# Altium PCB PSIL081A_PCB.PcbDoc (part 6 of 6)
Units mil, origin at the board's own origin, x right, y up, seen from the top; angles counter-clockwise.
Board outline 14000 x 8000 mil, 10 copper layers (Top Layer, Signal Layer 1, Signal Layer 2, Signal Layer 3, Signal Layer 4, Signal Layer 5, Signal Layer 6, Signal Layer 7, Signal Layer 8, Bottom Layer), stack 60.9 mil thick; 433 components, 510 nets, 1716 pads, 590 vias.
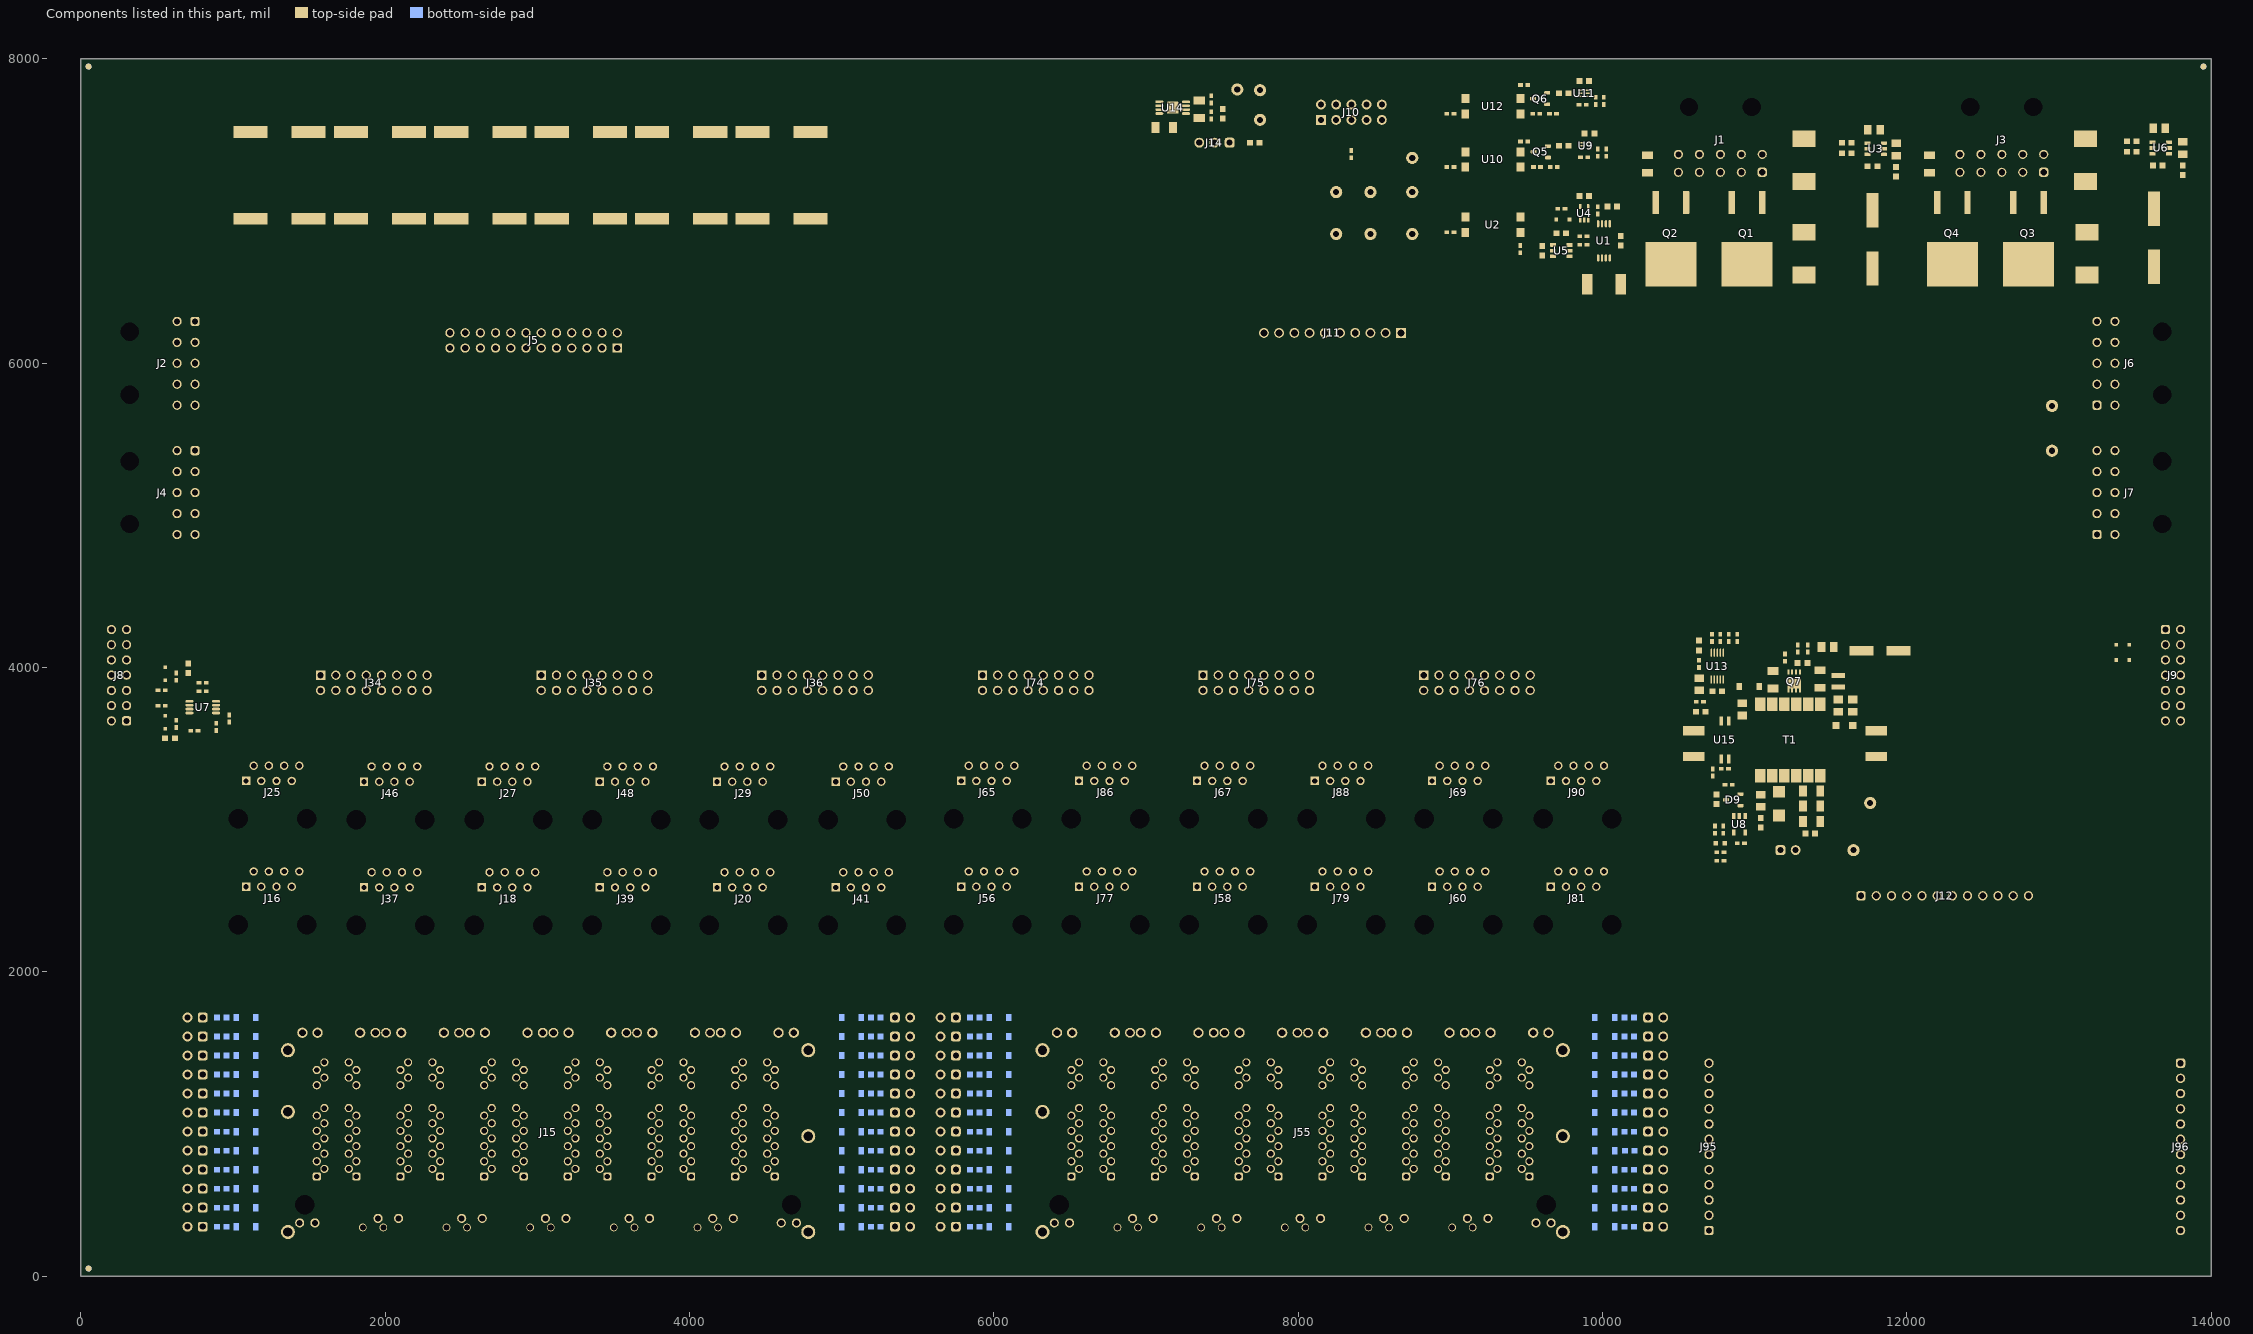
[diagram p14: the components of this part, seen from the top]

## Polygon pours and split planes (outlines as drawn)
55VDC on Signal Layer 4 "SIGNAL_LAYER_4_55VDC_P033" (solid, remove dead copper, pour order 33): 700,6500 1325,6500 2025,5800 10050,5800 10050,6590 10250,6590 10250,6800 11150,6800 11150,6700 11500,6700 11500,6800 13000,6800 13000,6700 13350,6700 13350,6800 13950,6800 13950,6400 13300,6400 13300,4650 700,4650
VPWR on Signal Layer 4 "SIGNAL_LAYER_4_VPWR_P028" (solid, remove dead copper, pour order 28): 7850,7950 7850,6590 9950,6590 9950,5850 2050,5850 1350,6550 50.04,6550 50,7950 6400,7950
3.3V_ISO on Signal Layer 4 "SIGNAL_LAYER_4_3.3V_ISO_P015" (solid, remove dead copper, pour order 15): 270,4600 270,3500 800,3500 1100,3800 1100,4300 12099.95,4300 12100,3445 11600,3445 11600,2900 11000,2900 11000,2450 13730,2450 13730,4600
VIN1 on Signal Layer 4 "SIGNAL_LAYER_4_VIN1_P023" (solid, remove dead copper, pour order 23): 10250,6950 10250,7300 11450,7300 11450,6950
VIN2 on Signal Layer 4 "SIGNAL_LAYER_4_VIN2_P024" (solid, remove dead copper, pour order 24): 12100,6950 13325,6950 13325,7300 12100,7300
GND on Signal Layer 6 "SIGNAL_LAYER_6_GND_P044" (solid, remove dead copper, pour order 44): 10540,2540 10420,2540 10420,3555 12025,3555 12025,4650 13850,4650 13850,3690 13770,3690 13770,3600 13950,3600 13950,7950 9400,7950 9400,6590 7850,6590 7850,7950 50,7950 50,50 1200,50 1200,450 9900,450 9900,50 10540,50
GND_ISO on Signal Layer 6 "SIGNAL_LAYER_6_GND_ISO_P052" (solid, remove dead copper, pour order 52): 10650,2650 10530,2650 10530,3445 10650,3445 12100,3445 12100,4575 13730,4575 13730,3480 13950,3480 13950,50 10650,50
VPWR on Top Layer "TOP_LAYER_VPWR_P027" (solid, remove dead copper, pour order 27): 7000,7350 7000.96,7349.04 7850,7349.04 7850,6590 9950,6590 9950,5850 2050,5850 1350,6550 50,6550 50,7950 7000,7950
NetQ7_1 on Top Layer "TOP_LAYER_NETQ7_1_P007" (solid, remove dead copper, pour order 7): 11305,3955 11305,4055 11240,4055 11240,3955
NetD7_2 on Top Layer "TOP_LAYER_NETD7_2_P006" (solid, remove dead copper, pour order 6): 11310,3710 11310,3930 11210,3930 11210,3835 11240,3835 11240,3710
NetC31_1 on Top Layer "TOP_LAYER_NETC31_1_P005" (solid, remove dead copper, pour order 5): 11100,3070 11100,2925 11235,2925 11235,2750 11350,2750 11350,3215 11332.15,3232.85 11255,3232.85 11255,3070
NetD6_2 on Top Layer "TOP_LAYER_NETD6_2_P004" (solid, remove dead copper, pour order 4): 11000,3350 11000,3140 11230,3140 11230,3350
55VDC on Top Layer "TOP_LAYER_55VDC_P032" (solid, remove dead copper, pour order 32): 11800,4350 12025,4350 12025,4650 13300,4650 13300,6400 13950,6400 13950,6800 13350,6800 13350,6700 13000,6700 13000,6800 11500,6800 11500,6700 11150,6700 11150,6800 10250,6800 10250,6590 10050,6590 10050,5800 2025,5800 1325,6500 700,6500 700,4350 11495,4350 11495,3929.78 11800,3929.78
VIN2 on Top Layer "TOP_LAYER_VIN2_P019" (solid, remove dead copper, pour order 19): 12100,6950 12100,7300 13325,7300 13325,6950 13000,6950
VIN1 on Top Layer "TOP_LAYER_VIN1_P018" (solid, remove dead copper, pour order 18): 11450,7300 11450,6950 11150,6950 10250,6950 10250,7300
BSP on Top Layer "TOP_LAYER_BSP_P056" (solid, remove dead copper, pour order 56): 4900,350 4900,200 6200,200 6200,350 9800,350 9800,50 1300,50 1300,350
GND on Top Layer "TOP_LAYER_GND_P009" (solid, remove dead copper, pour order 9): 1000,7675 1250,7675 1250,6795 1000,6795
GND on Top Layer "TOP_LAYER_GND_P010" (solid, remove dead copper, pour order 10): 1660,7675 1910,7675 1910,6795 1660,6795
GND on Top Layer "TOP_LAYER_GND_P011" (solid, remove dead copper, pour order 11): 2320,7675 2570,7675 2570,6795 2320,6795
GND on Top Layer "TOP_LAYER_GND_P012" (solid, remove dead copper, pour order 12): 2980,7675 3230,7675 3230,6795 2980,6795
GND on Top Layer "TOP_LAYER_GND_P013" (solid, remove dead copper, pour order 13): 3640,7675 3890,7675 3890,6795 3640,6795
GND on Top Layer "TOP_LAYER_GND_P014" (solid, remove dead copper, pour order 14): 4300,7675 4550,7675 4550,6795 4300,6795
GND on Top Layer "TOP_LAYER_GND_P035" (solid, remove dead copper, pour order 35): 10250,7950 10250,7330 11175,7330 11175,6725 11475,6725 11475,6825 12075,6825 12075,7330 13025,7330 13025,6725 13325,6725 13325,6825 13950,6825 13950,7950
GND on Top Layer "TOP_LAYER_GND_P036" (solid, remove dead copper, pour order 36): 13950,4650 13325,4650 13325,6375 13950,6375
GND on Top Layer "TOP_LAYER_GND_P037" (solid, remove dead copper, pour order 37): 675,4650 675,6500 50,6500 50,4650
NetC32_2 on Top Layer "TOP_LAYER_NETC32_2_P008" (solid, remove dead copper, pour order 8): 11395,3715 11395,3885 11680,3885 11680,3765 11490,3765 11490,3715
GND_ISO on Top Layer "TOP_LAYER_GND_ISO_P051" (solid, remove dead copper, pour order 51): 10650,2650 10650,50 13950,50 13950,3480 13730,3480 13730,4575 12100,4575 12100,3445 10650,3445 10530,3445 10530,2650
GND_ISO on Signal Layer 3 "SIGNAL_LAYER_3_GND_ISO_P016" (solid, remove dead copper, pour order 16): 10650,2650 10530,2650 10530,3445 12100,3445 12100,4575 13730,4575 13730,3480 13950,3480 13950,50 10650,50
GND on Signal Layer 3 "SIGNAL_LAYER_3_GND_P045" (solid, remove dead copper, pour order 45): 10540,2540 10420,2540 10420,3555 12025,3555 12025,4650 13850,4650 13850,3690 13770,3690 13770,3600 13950,3600 13950,7950 9400,7950 9400,6590 7855,6590 7850,6595 7850,7950 50,7950 50,50 1200,50 1200,450 9900,450 9900,50 10540,50
VIN2 on Signal Layer 2 "SIGNAL_LAYER_2_VIN2_P022" (solid, remove dead copper, pour order 22): 12100,6950 12100,7300 13325,7300 13325,6950
VIN1 on Signal Layer 2 "SIGNAL_LAYER_2_VIN1_P021" (solid, remove dead copper, pour order 21): 10250,7300 10250,6950 11450,6950 11450,7300
55VDC on Signal Layer 2 "SIGNAL_LAYER_2_55VDC_P031" (solid, remove dead copper, pour order 31): 12025,4650 12025,4350 700,4350 700,6500 1325,6500 2025,5800 10050,5800 10050,6590 10249.7,6590.3 10249.7,6800 11149.7,6799.7 11149.7,6700 11500,6700 11500,6800 12999.7,6799.7 12999.7,6700 13350,6700 13350,6800 13950,6800 13950,6400 13300,6400 13300,4650
VPWR on Signal Layer 2 "SIGNAL_LAYER_2_VPWR_P029" (solid, remove dead copper, pour order 29): 9950,6590 7850,6590 7850,7950 7000,7950 50,7950 50,6550 1350,6550 2050,5850 9950,5850
GND on Signal Layer 2 "SIGNAL_LAYER_2_GND_P041" (solid, remove dead copper, pour order 41): 50,6500 50,4650 675,4650 675,6500
GND on Signal Layer 2 "SIGNAL_LAYER_2_GND_P043" (solid, remove dead copper, pour order 43): 13950,6375 13325,6375 13325,4650 13950,4650
GND on Signal Layer 2 "SIGNAL_LAYER_2_GND_P042" (solid, remove dead copper, pour order 42): 10250,7950 13950,7950 13950,6825 13325,6825 13325,6725 13025,6725 13025,7330 12075,7330 12075,6825 11475,6825 11475,6725 11175,6725 11175,7330 10250,7330
GND_ISO on Signal Layer 2 "SIGNAL_LAYER_2_GND_ISO_P053" (solid, remove dead copper, pour order 53): 10650,2650 10530,2650 10530,3445 12100,3445 12100,4575 13730,4575 13730,3480 13950,3480 13950,50 10650,50
GND on Signal Layer 1 "SIGNAL_LAYER_1_GND_P046" (solid, remove dead copper, pour order 46): 10540,2540 10420,2540 10420,3555 12025,3555 12025,4650 13850,4650 13850,3690 13770,3690 13770,3600 13950,3600 13950,7950 9400,7950 9400,6590 7850,6590 7850,7950 50,7950 50,50 1200,50 1200,450 9900,450 9900,50 10540,50
GND_ISO on Signal Layer 1 "SIGNAL_LAYER_1_GND_ISO_P050" (solid, remove dead copper, pour order 50): 10650,2650 10530,2650 10530,3445 12100,3445 12100,4575 13730,4575 13730,3480 13950,3480 13950,50 10650,50
BSP on Bottom Layer "BOTTOM_LAYER_BSP_P058" (solid, remove dead copper, pour order 58): 1300,350 4900,349.84 4900,200 6200,200 6200,349.84 9800,349.84 9800,50 1300,50
VPWR on Bottom Layer "BOTTOM_LAYER_VPWR_P030" (solid, remove dead copper, pour order 30): 50,7950 7850,7950 7850,6590 9950,6590 9950,5850 2050,5850 1350,6550 50,6550
VIN1 on Bottom Layer "BOTTOM_LAYER_VIN1_P025" (solid, remove dead copper, pour order 25): 10250,6950 11450,6950 11450,7300 10250,7300
VIN2 on Bottom Layer "BOTTOM_LAYER_VIN2_P026" (solid, remove dead copper, pour order 26): 12100,6950 12100,7300 13325,7300 13325,6950
GND on Bottom Layer "BOTTOM_LAYER_GND_P038" (solid, remove dead copper, pour order 38): 10250,7950 10250,7330 11175,7330 11175,6725 11475,6725 11475,6825 12075,6825 12075,7330 13025,7330 13025,6725 13325,6725 13325,6825 13950,6825 13950,7950
GND on Bottom Layer "BOTTOM_LAYER_GND_P039" (solid, remove dead copper, pour order 39): 13325,4650 13325,6375 13950,6375 13950,4650
GND on Bottom Layer "BOTTOM_LAYER_GND_P040" (solid, remove dead copper, pour order 40): 50,6500 675,6500 675,4650 50,4650
55VDC on Bottom Layer "BOTTOM_LAYER_55VDC_P034" (solid, remove dead copper, pour order 34): 12025,4650 12025,4350 700,4350 700,4650 700,6500 1325,6500 2025,5800 10050,5800 10050,6590 10250,6590 10250,6800 11150,6800 11150,6700 11500,6700 11500,6800 13000,6800 13000,6700 13350,6700 13350,6800 13950,6800 13950,6400 13300,6400 13300,4650
GND_ISO on Bottom Layer "BOTTOM_LAYER_GND_ISO_P060" (solid, remove dead copper, pour order 60): 10650,50 10650,2650 10530,2650 10530,3445 12100,3445 12100,4575 13730,4575 13730,3480 13950,3480 13950,50
GND on Signal Layer 8 "SIGNAL_LAYER_8_GND_P048" (solid, remove dead copper, pour order 48): 13850,3690 13770,3690 13770,3600 13850,3600 13950,3600 13950,7950 9400,7950 9400,6600 9400,4820 13850,4820
GND_ISO on Signal Layer 8 "SIGNAL_LAYER_8_GND_ISO_P047" (solid, remove dead copper, pour order 47): 10650,2650 10530,2650 10530,3445 10650,3445 12100,3445 12099.96,4250 10950,4250 10950,4345 10500,4345 10500,4250 1100,4250 1100,3800 800,3500 270,3500 270,4700 7950,4700 7950,7850 9275,7850 9275,4700 12100,4700 13730,4700 13730,3480 13950,3480 13950,50 10650,50
GND on Signal Layer 5 "SIGNAL_LAYER_5_GND_P049" (solid, remove dead copper, pour order 49): 10540,2540 10420,2540 10420,3555 12025,3555 12025,4650 13850,4650 13850,3600 13950,3600 13950,7950 9400,7950 9400,6590 7850,6590 7850,7950 50,7950 50,50 1200,50 1200,450 9900,450 9900,50 10540,50
GND_ISO on Signal Layer 5 "SIGNAL_LAYER_5_GND_ISO_P064" (solid, remove dead copper, pour order 64): 10650,50 10650,2650 10530,2650 10530,3445 12100,3445 12100,4575 13730,4575 13730,3480 13950,3480 13950,50
GND_ISO on Signal Layer 7 "SIGNAL_LAYER_7_GND_ISO_P062" (solid, remove dead copper, pour order 62): 10650,50 10650,2650 10530,2650 10530,3445 12100,3445 12100,4575 13730,4575 13730,3480 13950,3480 13950,50

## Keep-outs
Keep-Out Layer:
  text ".Layer_Name" at 577,-858.49 h60

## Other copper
Top Layer:
  text ".Layer_Name" at 577,-853.49 h60
Signal Layer 1:
  text ".Layer_Name" at 577,-858.49 h60
Signal Layer 2:
  text ".Layer_Name" at 577,-858.49 h60
Signal Layer 3:
  text ".Layer_Name" at 577,-853.49 h60
Signal Layer 4:
  text ".Layer_Name" at 577,-853.49 h60
Signal Layer 5:
  text ".Layer_Name" at 577,-853.49 h60
Signal Layer 6:
  text ".Layer_Name" at 577,-853.49 h60
Signal Layer 7:
  text ".Layer_Name" at 577,-853.49 h60
Signal Layer 8:
  text ".Layer_Name" at 577,-853.49 h60
Bottom Layer:
  text ".Layer_Name" at 577,-858.49 h60

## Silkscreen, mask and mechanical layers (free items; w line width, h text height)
Top Overlay:
  lines w7: 9795,7065 9820,7040 ; 9800,7490 9835,7455 ; 9935,7795 9995,7795 10010,7810 ; 11875,7490 11885,7500 11885,7535 ; 13750,7500 13750,7515 13775,7540 13775,7555
  text "'.PRJ_Number'.PCB_Rev-" at 6430,7760 h108.27
  text "PSEMTHR24EVM-081" at 5088.24,7533 h108.27
  text ".Layer_Name" at 577,-858.49 h60
Bottom Overlay:
  lines w7: 4610,1675 4865,1675 ; 4665,200 4920,200 ; 4800,1675 4800,1625 4850,1575 4885,1575 ; 4870,200 4870,370 4915,415
  text ".Layer_Name" at 577,-858.49 h60
Top Paste:
  text ".Layer_Name" at 577,-858.49 h60
Bottom Paste:
  text ".Layer_Name" at 577,-858.49 h60
Top Solder:
  text ".Layer_Name" at 577,-858.49 h60
  text ".Layer_Name" at 577,-858.49 h60
Bottom Solder:
  text ".Layer_Name" at 577,-858.49 h60
Drill Guide:
  text ".Layer_Name" at 577,-858.49 h60
M1 Board Outline:
  the board outline again, w10
  text ".Layer_Name" at 577,-858.49 h60
M2 Board Dimensions:
  rectangle: 0,-275 125,-150
  rectangle: 125,-400 500,-275
  lines w7: 0,-275 1000,-275 ; 125,-400 125,-150 ; 250,-400 250,-150 ; 500,-400 500,-150 ; 750,-400 750,-150 ; 0,-400 1000,-400 1000,-150 0,-150 0,-400
  text ".Layer_Name" at 577,-858.49 h60
M3 3D STEP Top:
  text ".Layer_Name" at 577,-858.49 h60
M4 3D STEP Bottom:
  text ".Layer_Name" at 577,-858.49 h60
M5 Assembly Top:
  lines w10: -292,-930.17 6308,-930.17 ; -292,-726.83 6310,-726.83 ; -292,-523.5 -292,-1133.5 3713,-1133.5 6310,-1133.5 6310,-523.5 -291.5,-523.5 -291.5,-1133.5 1284,-1133.5 ; 2173,-1133.5 2173,-523.5 ; 3440,-726.83 3440,-523.5 ; 4280,-726.83 4280,-523.5 ; 4902,-1140 4902,-937.17
  text "COMPONENTS MARKED 'DNP' SHOULD NOT BE POPULATED." at 1153.5,-318.5 h60
  text "ASSEMBLY VARIANT:" at 1153,-434 h60
  text ".VariantName" at 2189,-434 h60
  text "PCB VIEWED FROM TOP SIDE" at -228.5,-655.67 h60
  text "BOARD #:" at 2248,-655.67 h60
  text ".PRJ_Number" at 2793.5,-655.67 h60
  text "REV:" at 3638,-655.67 h60
  text ".PCB_Rev" at 3929.5,-655.67 h60
  text "SVN REV:" at 4476,-655.67 h60
  text ".VersionControl_RevNumber" at 4982,-655.67 h60
  text "PLOT NAME =" at -228.5,-1064.34 h60
  text ".plot_File_Name" at 577,-1064.34 h60
  text "GENERATED    :" at 2250,-1064.34 h60
  text ".Print_Date" at 3119.5,-1064.34 h60
  text ".Print_Time" at 3848.5,-1064.34 h60
  text "TEXAS INSTRUMENTS" at 5113,-1064.34 h60
M6 Assembly Bottom:
  lines w10: -292.5,-727.33 6309.5,-727.33 ; -290.5,-930.67 6309.5,-930.67 ; 1115.5,-1140.5 1115.5,-937.67 ; 1737.5,-727.33 1737.5,-524 ; 2577.5,-727.33 2577.5,-524 ; 3844.5,-1134 3844.5,-524 ; 4733.5,-1134 6309,-1134 6309,-524 -292.5,-524 -292.5,-1134 2304.5,-1134 6309.5,-1134 6309.5,-524
  text "COMPONENTS MARKED 'DNP' SHOULD NOT BE POPULATED." at 6102,-318 h60
  text ".VariantName" at 5058,-434 h60
  text "ASSEMBLY VARIANT:" at 6097,-434 h60
  text ".VersionControl_RevNumber" at 1035.5,-656.17 h60
  text "SVN REV:" at 1541.5,-656.17 h60
  text ".PCB_Rev" at 2088,-656.17 h60
  text "REV:" at 2379.5,-656.17 h60
  text ".PRJ_Number" at 3224,-656.17 h60
  text "BOARD #:" at 3769.5,-656.17 h60
  text "PCB VIEWED FROM BOTTOM SIDE" at 6246,-656.17 h60
  text "TEXAS INSTRUMENTS" at 904.5,-1064.84 h60
  text ".Print_Time" at 2169,-1064.84 h60
  text ".Print_Date" at 2898,-1064.84 h60
  text "GENERATED    :" at 3767.5,-1064.84 h60
  text ".plot_File_Name" at 5440.5,-1064.84 h60
  text "PLOT NAME =" at 6246,-1064.84 h60
M9 Title Sheet:
  drawing of 56 lines, arcs and shapes, not listed
  text "1" at 1058.34,13381.39 h70
  text "2" at 4384,13381.39 h70
  text "3" at 7714,13381.39 h70
  text "4" at 11049,13381.39 h70
  text "5" at 14374,13381.39 h70
  text "6" at 17709,13381.39 h70
  text "A" at -463,11603.39 h70
  text "A" at 19237,11603.39 h70
  text "B" at -463,7853.39 h70
  text "B" at 19237,7853.39 h70
  text "C" at -463,4103.39 h70
  text "C" at 19237,4103.39 h70
  text "D" at -463,353.39 h70
  text "D" at 19237,353.39 h70
  text "PROJECT TITLE:" at 16143,268.39 h45
  text ".PRJ_Title" at 16193,135.06 h70
  text "DESIGNED FOR:" at 16143,-32.61 h45
  text ".PRJ_Customer" at 16193,-172.61 h70
  text "FILE NAME:" at 16143,-332.61 h45
  text ".PCB_File_Name_No_Path" at 16193,-452.61 h70
  text "Texas Instruments (TI) and/or its licensors do not warrant the accuracy or completeness of this specification" at 11173.5,-614.45 h45
  text "ENGINEER:" at 16143,-622.61 h45
  text "LAYOUT BY:" at 17648,-622.61 h45
  text "or any information contained therein. TI and/or its licensors do not warrant that this design will meet" at 11128.51,-727.11 h45
  text ".PRJ_Engineer" at 16193,-777.6 h70
  text ".PCB_Layout" at 17698.5,-777.6 h70
  text "the specifications, will be suitable for your application or fit for any particular purpose, or will operate in" at 11128.51,-839.78 h45
  text ".Layer_Name" at 577,-858.49 h60
  text "ALTIUM DESIGNER VERSION:" at 17648,-932.61 h45
  text "an implementation. TI and/or its licensors do not warrant that the design is production worthy. You should" at 11128.51,-952.44 h45
  text "completely validate and test your design implementation to confirm the system functionality for your application." at 11173.5,-1065.11 h45
  text ".print_Scale" at 16193,-1065.94 h70
  text ".Application_BuildNumber" at 17698.5,-1065.94 h70
  text "1" at 1058.34,-1318.61 h70
  text "2" at 4384,-1318.61 h70
  text "3" at 7714,-1318.61 h70
  text "4" at 11049,-1318.61 h70
  text "5" at 14374,-1318.61 h70
  text "6" at 17709,-1318.61 h70
M10 Fab Notes:
  drawing of 189 lines, arcs and shapes, not listed
  text "DESIGN INFORMATION" at 17178.02,6365.17 h60
  text "MIN. TRACK WIDTH:" at 16533.46,6233.05 h60
  text "7" at 17629.7,6233.05 h60
  text "MIL" at 17784.46,6233.05 h60
  text "MIN. CLEARANCE:" at 16533.46,6108.92 h60
  text "0.2" at 17569.7,6108.93 h60
  text "mm" at 17784.46,6108.92 h60
  text "MIN. VIA PAD SIZE:" at 16533.46,5984.8 h60
  text "24" at 17599.71,5984.8 h60
  text "MIL" at 17784.46,5984.8 h60
  text "0.05mm (2MIL)" at 17228.46,5854.9 h60
  text "MINIMUM ANNULAR RING" at 16204.23,5846.67 h60
  text "EXTERNAL" at 17936.46,5846.67 h60
  text "PER" at 16404.23,5736.55 h60
  text "IPC-D-275 CLASS 2 LEVEL C" at 16624.23,5736.54 h60
  text "MIL, HOLES" at 18112.46,5636.07 h60
  text "+/-" at 17720,5627.48 h60
  text "+/-" at 18574,5627.48 h60
  text "REGISTRATION TOLERANCES:" at 16204.23,5626.42 h60
  text "METAL" at 17404,5626.42 h60
  text "5" at 17980.2,5626.42 h60
  text "3" at 18813.2,5626.42 h60
  text "MIL" at 18929.46,5626.42 h60
  text "HOLE SIZE TOLERANCE (UNLESS OTHERWISE SPECIFIED):" at 16204.23,5528.1 h60
  text "+/-" at 18574,5525.23 h60
  text "3" at 18813.2,5524.17 h60
  text "MIL" at 18929.46,5524.17 h60
  text "MATERIAL:" at 16129.46,5386.52 h60
  text "FR-4 High Tg" at 17115.9,5258 h60
  text "X" at 16971.46,5250.01 h60
  text "FR-408" at 16550.46,5245.49 h60
  text "OTHER" at 18038.46,5245.49 h60
  text "62 MIL (1.6mm) +/-10%" at 16870.56,5102.46 h60
  text "X" at 16750,5100 h60
  text "THICKNESS:" at 16204.23,5094.24 h60
  text "OTHER" at 18155.46,5094.24 h60
  text "TOLERANCE:" at 16204.23,4955.92 h60
  text "X" at 17052.46,4955.92 h60
  text "ANSI IPC-6012 TYPE 3 CLASS 2" at 17230.48,4955.92 h60
  text "OTHER +/-" at 17230.46,4811.73 h60
  text "BOW & TWIST:" at 16204.23,4666.54 h60
  text "X" at 17052.46,4666.54 h60
  text "ANSI IPC-6012 TYPE 3 CLASS 2" at 17230.48,4666.54 h60
  text "OTHER +/-" at 17230.46,4519.85 h60
  text "DRILLING:" at 16129.46,4389.23 h60
  text "NC_DRILL FILES" at 17890.46,4284.04 h60
  text "REFERENCE:" at 16204.23,4280.1 h60
  text "X" at 16861.46,4280.01 h60
  text "AS SHOWN" at 17039.46,4280.1 h60
  text "X" at 17762.46,4280.1 h60
  text "OTHER" at 18188.46,4137.85 h60
  text "PTH COPPER THICKNESS:" at 16203.91,4134.32 h60
  text "X" at 17343.14,4134.32 h60
  text "20-30 um" at 17471.14,4134.32 h60
  text "BOARD FINISH:" at 16129.46,3986.73 h60
  text "SILKSCREEN:" at 16284.68,3876.6 h60
  text "X" at 17242.46,3876.6 h60
  text "TOP" at 17359.46,3876.6 h60
  text "X" at 17752.46,3876.6 h60
  text "BOTTOM" at 17870.46,3876.6 h60
  text "SILKSCREEN COLOR:" at 16284.68,3721.41 h60
  text "X" at 17241.46,3721.41 h60
  text "WHITE" at 17359.46,3721.41 h60
  text "OTHER" at 17870.46,3721.41 h60
  text "X" at 17372.46,3577.96 h60
  text "GREEN" at 17490.46,3577.96 h60
  text "OTHER" at 18108.46,3577.96 h60
  text "SOLDER RESIST COLOR:" at 16284.68,3571.1 h60
  text "X" at 17372.46,3423.71 h60
  text "MATTE" at 17490.46,3423.71 h60
  text "SEMI-GLOSS" at 18108,3423.07 h60
  text "IMMERSION GOLD (ENIG)" at 17190.46,3250.94 h60
  text "ENEPIG" at 18528,3243.72 h60
  text "SURFACE FINISH:" at 16129.46,3242.72 h60
  text "X" at 17012.46,3242.72 h60
  text "IMM. TIN/SILVER OR EQUIV" at 16459,3105.4 h60
  text "OTHER" at 17890.46,3101.47 h60
  text "ARRAY/PANEL:" at 16129.46,2946.09 h60
  text "X" at 17025,2945 h60
  text "CUT AND TRIM PER M1 BOARD OUTLINE" at 17190.46,2937.87 h60
  text "N.C. ROUTE" at 17190.46,2801.9 h60
  text "V. SCORE" at 18056.46,2801.9 h60
  text "CERTIFICATION:" at 16129.46,2672.77 h60
  text "MATERIALS AND WORKMANSHIP FOR ALL PCBS" at 16854.46,2672.77 h60
  text "TO MEET OR EXCEED THE REQUIREMENTS OF:" at 16854.46,2578.71 h60
  text "X" at 16491.97,2450.08 h60
  text "ANSI IPC-A-600F CLASS ->" at 16619.96,2450.08 h60
  text "X" at 18267.97,2450.08 h60
  text "2" at 18377.96,2450.08 h60
  text "1" at 18062.96,2448.58 h60
  text "3" at 18731.96,2448.58 h60
  text "X" at 17303.97,2302.39 h60
  text "RoHS" at 17431.96,2302.39 h60
  text "OTHER" at 18076.36,2302.39 h60
  text "PER ORDER" at 18473.42,2302.39 h60
  text "ALL BOARDS MUST MEET OR EXCEED UL94-V0 REQUIREMENTS." at 16157,2148.57 h60
  text "PCB MUST BEAR THE UL94V-0 UL REGISTERED MATERIAL ID NUMBER" at 16157,2032.5 h60
  text "ADDITIONAL REQUIREMENTS:" at 16129.46,1863.08 h60
  text "MICROSECTION:" at 16204.23,1755.95 h60
  text "YES" at 17109.96,1755.95 h60
  text "REQUIRED" at 17971.46,1611.62 h60
  text "BARE BOARD ELEC. TEST:" at 16204.23,1608.76 h60
  text "NONE" at 17509.96,1608.76 h60
  text "X" at 17853.46,1608.76 h60
  text "PER ORDER" at 18563.46,1608.76 h60
  text "XX MIL VIAS REQUIRE NON-CONDUCTIVE FILL AND PLANARIZE" at 16372.38,1403.82 h59
  text "XX MIL VIAS REQUIRE CONDUCTIVE FILL AND PLANARIZE" at 16380.38,1299.84 h60
  text "OUTER XX MIL TRACES REQUIRE 50 OHM SINGLE-ENDED IMPEDANCE" at 16379.39,1136.46 h58
  text "LAYER 2 & 3 (INNER LAYERS) XX MIL WIDE, XX MIL SPACE / TRACES REQUIRE 100 OHM DIFFERENTIAL IMPEDANCE" at 16371.39,900.74 h60
  text ".Layer_Name" at 577,-858.49 h60
M11 Gerber Information:
  lines w10: -292,-930.17 6308,-930.17 ; -292,-726.83 6310,-726.83 ; -292,-523.5 -292,-1133.5 3713,-1133.5 6310,-1133.5 6310,-523.5 -291.5,-523.5 -291.5,-1133.5 1284,-1133.5 ; 2173,-1133.5 2173,-523.5 ; 3440,-726.83 3440,-523.5 ; 4280,-726.83 4280,-523.5 ; 4902,-1140 4902,-937.17
  text "ALL ARTWORK VIEWED FROM TOP SIDE" at -228.5,-655.67 h60
  text "BOARD #:" at 2248,-655.67 h60
  text ".PRJ_Number" at 2793.5,-655.67 h60
  text "REV:" at 3638,-655.67 h60
  text ".PCB_Rev" at 3929.5,-655.67 h60
  text "SVN REV:" at 4476,-655.67 h60
  text ".VersionControl_RevNumber" at 4982,-655.67 h60
  text "LAYER NAME =" at -228.5,-858.49 h60
  text "PLOT NAME =" at -228.5,-1064.34 h60
  text ".plot_File_Name" at 577,-1064.34 h60
  text "GENERATED    :" at 2250,-1064.34 h60
  text ".Print_Date" at 3119.5,-1064.34 h60
  text ".Print_Time" at 3848.5,-1064.34 h60
  text "TEXAS INSTRUMENTS" at 5113,-1064.34 h60
M12 Stackup:
  drawing of 607 lines, arcs and shapes, not listed
  text "Layer" at 14515.88,13014.68 h60
  text "Name" at 14925.8,13014.68 h60
  text "Material" at 15865.54,13014.68 h60
  text "Thickness" at 16725.3,13014.68 h60
  text "Constant" at 17375.14,13014.68 h60
  text "Board Layer Stack" at 17945,13014.68 h60
  text "1" at 14515.88,12894.68 h60
  text "Top Overlay" at 14925.8,12894.68 h60
  text "2" at 14515.88,12774.68 h60
  text "Top Solder" at 14925.8,12774.68 h60
  text "Solder Resist" at 15865.54,12774.68 h60
  text "0.40mil" at 16725.3,12774.68 h60
  text "3.5" at 17375.14,12774.68 h60
  text "3" at 14515.88,12654.68 h60
  text "Top Layer" at 14925.8,12654.68 h60
  text "Copper" at 15865.54,12654.68 h60
  text "1.90mil" at 16725.3,12654.68 h60
  text "4" at 14515.88,12534.68 h60
  text "Dielectric1" at 14925.8,12534.68 h60
  text "FR-4" at 15865.54,12534.68 h60
  text "5.80mil" at 16725.3,12534.68 h60
  text "4.2" at 17375.14,12534.68 h60
  text "5" at 14515.88,12414.68 h60
  text "Signal Layer 1" at 14925.8,12414.68 h60
  text "Copper" at 15865.54,12414.68 h60
  text "1.20mil" at 16725.3,12414.68 h60
  text "6" at 14515.88,12294.68 h60
  text "Dielectric 2" at 14925.8,12294.68 h60
  text "FR-4" at 15865.54,12294.68 h60
  text "5.00mil" at 16725.3,12294.68 h60
  text "4.2" at 17375.14,12294.68 h60
  text "7" at 14515.88,12174.68 h60
  text "Signal Layer 2" at 14925.8,12174.68 h60
  text "Copper" at 15865.54,12174.68 h60
  text "1.20mil" at 16725.3,12174.68 h60
  text "8" at 14515.88,12054.68 h60
  text "Dielectric 3" at 14925.8,12054.68 h60
  text "FR-4" at 15865.54,12054.68 h60
  text "5.20mil" at 16725.3,12054.68 h60
  text "4.2" at 17375.14,12054.68 h60
  text "9" at 14515.88,11934.68 h60
  text "Signal Layer 3" at 14925.8,11934.68 h60
  text "Copper" at 15865.54,11934.68 h60
  text "1.20mil" at 16725.3,11934.68 h60
  text "10" at 14515.88,11814.68 h60
  text "Dielectric 4" at 14925.8,11814.68 h60
  text "FR-4" at 15865.54,11814.68 h60
  text "5.00mil" at 16725.3,11814.68 h60
  text "4.2" at 17375.14,11814.68 h60
  text "11" at 14515.88,11694.68 h60
  text "Signal Layer 4" at 14925.8,11694.68 h60
  text "Copper" at 15865.54,11694.68 h60
  text "1.20mil" at 16725.3,11694.68 h60
  text "12" at 14515.88,11574.68 h60
  text "Dielectric 5" at 14925.8,11574.68 h60
  text "FR-4" at 15865.54,11574.68 h60
  text "5.50mil" at 16725.3,11574.68 h60
  text "4.2" at 17375.14,11574.68 h60
  text "13" at 14515.88,11454.68 h60
  text "Signal Layer 5" at 14925.8,11454.68 h60
  text "Copper" at 15865.54,11454.68 h60
  text "1.20mil" at 16725.3,11454.68 h60
  text "14" at 14515.88,11334.68 h60
  text "Dielectric 6" at 14925.8,11334.68 h60
  text "FR-4" at 15865.54,11334.68 h60
  text "5.00mil" at 16725.3,11334.68 h60
  text "4.2" at 17375.14,11334.68 h60
  text "15" at 14515.88,11214.68 h60
  text "Signal Layer 6" at 14925.8,11214.68 h60
  text "Copper" at 15865.54,11214.68 h60
  text "1.20mil" at 16725.3,11214.68 h60
  text "16" at 14515.88,11094.68 h60
  text "Dielectric 7" at 14925.8,11094.68 h60
  text "FR-4" at 15865.54,11094.68 h60
  text "5.20mil" at 16725.3,11094.68 h60
  text "4.2" at 17375.14,11094.68 h60
  text "17" at 14515.88,10974.68 h60
  text "Signal Layer 7" at 14925.8,10974.68 h60
  text "Copper" at 15865.54,10974.68 h60
  text "1.20mil" at 16725.3,10974.68 h60
  text "18" at 14515.88,10854.68 h60
  text "Dielectric 8" at 14925.8,10854.68 h60
  text "FR-4" at 15865.54,10854.68 h60
  text "5.00mil" at 16725.3,10854.68 h60
  text "4.2" at 17375.14,10854.68 h60
  text "19" at 14515.88,10734.68 h60
  text "Signal Layer 8" at 14925.8,10734.68 h60
  text "Copper" at 15865.54,10734.68 h60
  text "1.20mil" at 16725.3,10734.68 h60
  text "20" at 14515.88,10614.68 h60
  text "Dielectric 9" at 14925.8,10614.68 h60
  text "FR-4" at 15865.54,10614.68 h60
  text "5.80mil" at 16725.3,10614.68 h60
  text "4.2" at 17375.14,10614.68 h60
  text "21" at 14515.88,10494.68 h60
  text "Bottom Layer" at 14925.8,10494.68 h60
  text "Copper" at 15865.54,10494.68 h60
  text "1.90mil" at 16725.3,10494.68 h60
  text "22" at 14515.88,10374.68 h60
  text "Bottom Solder" at 14925.8,10374.68 h60
  text "Solder Resist" at 15865.54,10374.68 h60
  text "0.40mil" at 16725.3,10374.68 h60
  text "3.5" at 17375.14,10374.68 h60
  text "23" at 14515.88,10254.68 h60
  text "Bottom Overlay" at 14925.8,10254.68 h60
  text ".Layer_Name" at 577,-858.49 h60
M13 Component Bodies Top:
  text ".Layer_Name" at 577,-858.49 h60
M14 Component Bodies Bottom:
  text ".Layer_Name" at 577,-858.49 h60
M15 Courtyards Top:
  text ".Layer_Name" at 577,-858.49 h60
M16 Courtyards Bottom:
  text ".Layer_Name" at 577,-858.49 h60
Drill Drawing:
  drawing of 152 lines, arcs and shapes, not listed
  text "Symbol" at 15290.68,9463.88 h72
  text "Quantity" at 15591.51,9463.88 h72
  text "Finished Hole Size" at 15923.62,9463.88 h72
  text "Plated" at 16560.62,9463.88 h72
  text "Hole Type" at 16819.98,9463.88 h72
  text "Drill Layer Pair" at 17195.4,9463.88 h72
  text "Hole Tolerance" at 17919.25,9463.88 h72
  text "12" at 15591.51,9339.42 h60
  text "120.08mil (3.050mm)" at 15923.62,9339.42 h60
  text "NPTH" at 16560.62,9339.42 h60
  text "Round" at 16819.98,9339.42 h60
  text "Top Layer - Bottom Layer" at 17195.4,9339.42 h60
  text "+/-3.00mil" at 17919.25,9339.42 h60
  text "B" at 15265.37,9329.43 h55.31
  text "4" at 15591.51,9214.96 h60
  text "127.95mil (3.250mm)" at 15923.62,9214.96 h60
  text "NPTH" at 16560.62,9214.96 h60
  text "Round" at 16819.98,9214.96 h60
  text "Top Layer - Bottom Layer" at 17195.4,9214.96 h60
  text "+3.15mil/-1.97mil" at 17919.25,9214.96 h60
  text "48" at 15591.51,9090.5 h60
  text "128.00mil (3.251mm)" at 15923.62,9090.5 h60
  text "NPTH" at 16560.62,9090.5 h60
  text "Round" at 16819.98,9090.5 h60
  text "Top Layer - Bottom Layer" at 17195.4,9090.5 h60
  text "5" at 15591.51,8966.04 h60
  text "7.87mil (0.200mm)" at 15923.62,8966.04 h60
  text "PTH" at 16560.62,8966.04 h60
  text "Round" at 16819.98,8966.04 h60
  text "Top Layer - Bottom Layer" at 17195.4,8966.04 h60
  text "156" at 15591.51,8841.59 h60
  text "8.00mil (0.203mm)" at 15923.62,8841.59 h60
  text "PTH" at 16560.62,8841.59 h60
  text "Round" at 16819.98,8841.59 h60
  text "Top Layer - Bottom Layer" at 17195.4,8841.59 h60
  text "A" at 15265.37,8831.59 h55.31
  text "429" at 15591.51,8717.13 h60
  text "16.00mil (0.406mm)" at 15923.62,8717.13 h60
  text "PTH" at 16560.62,8717.13 h60
  text "Round" at 16819.98,8717.13 h60
  text "Top Layer - Bottom Layer" at 17195.4,8717.13 h60
  text "192" at 15591.51,8592.67 h60
  text "35.04mil (0.890mm)" at 15923.62,8592.67 h60
  text "PTH" at 16560.62,8592.67 h60
  text "Round" at 16819.98,8592.67 h60
  text "Top Layer - Bottom Layer" at 17195.4,8592.67 h60
  text "336" at 15591.51,8468.21 h60
  text "36.00mil (0.914mm)" at 15923.62,8468.21 h60
  text "PTH" at 16560.62,8468.21 h60
  text "Round" at 16819.98,8468.21 h60
  text "Top Layer - Bottom Layer" at 17195.4,8468.21 h60
  text "+/-3.00mil" at 17919.25,8468.21 h60
  text "48" at 15591.51,8343.75 h60
  text "40.00mil (1.016mm)" at 15923.62,8343.75 h60
  text "PTH" at 16560.62,8343.75 h60
  text "Round" at 16819.98,8343.75 h60
  text "Top Layer - Bottom Layer" at 17195.4,8343.75 h60
  text "+/-3.00mil" at 17919.25,8343.75 h60
  text "125" at 15591.51,8219.29 h60
  text "40.00mil (1.016mm)" at 15923.62,8219.29 h60
  text "PTH" at 16560.62,8219.29 h60
  text "Round" at 16819.98,8219.29 h60
  text "Top Layer - Bottom Layer" at 17195.4,8219.29 h60
  text "28" at 15591.51,8094.83 h60
  text "40.16mil (1.020mm)" at 15923.62,8094.83 h60
  text "PTH" at 16560.62,8094.83 h60
  text "Round" at 16819.98,8094.83 h60
  text "Top Layer - Bottom Layer" at 17195.4,8094.83 h60
  text "60" at 15591.51,7970.37 h60
  text "40.16mil (1.020mm)" at 15923.62,7970.37 h60
  text "PTH" at 16560.62,7970.37 h60
  text "Round" at 16819.98,7970.37 h60
  text "Top Layer - Bottom Layer" at 17195.4,7970.37 h60
  text "+/-1.57mil" at 17919.25,7970.37 h60
  text "156" at 15591.51,7845.92 h60
  text "40.95mil (1.040mm)" at 15923.62,7845.92 h60
  text "PTH" at 16560.62,7845.92 h60
  text "Round" at 16819.98,7845.92 h60
  text "Top Layer - Bottom Layer" at 17195.4,7845.92 h60
  text "48" at 15591.51,7721.46 h60
  text "45.00mil (1.143mm)" at 15923.62,7721.46 h60
  text "PTH" at 16560.62,7721.46 h60
  text "Round" at 16819.98,7721.46 h60
  text "Top Layer - Bottom Layer" at 17195.4,7721.46 h60
  text "+/-3.00mil" at 17919.25,7721.46 h60
  text "10" at 15591.51,7597 h60
  text "45.28mil (1.150mm)" at 15923.62,7597 h60
  text "PTH" at 16560.62,7597 h60
  text "Round" at 16819.98,7597 h60
  text "Top Layer - Bottom Layer" at 17195.4,7597 h60
  text "12" at 15591.51,7472.54 h60
  text "61.81mil (1.570mm)" at 15923.62,7472.54 h60
  text "PTH" at 16560.62,7472.54 h60
  text "Round" at 16819.98,7472.54 h60
  text "Top Layer - Bottom Layer" at 17195.4,7472.54 h60
  text "+/-9.84mil" at 17919.25,7472.54 h60
  text "1669 Total" at 15591.51,7348.08 h60
  text ".Layer_Name" at 577,-858.49 h60
M17 Embedded Cavity:
  text ".Layer_Name" at 577,-858.49 h60
M18 Embedded Assembly:
  text ".Layer_Name" at 577,-858.49 h60
M19 Embedded Keepout:
  text ".Layer_Name" at 567,-858.49 h60

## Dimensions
0,0 to 0,8000 on M2 Board Dimensions
0,0 to 14000,0 on M2 Board Dimensions
0,-400 to 1000,-400 on M2 Board Dimensions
